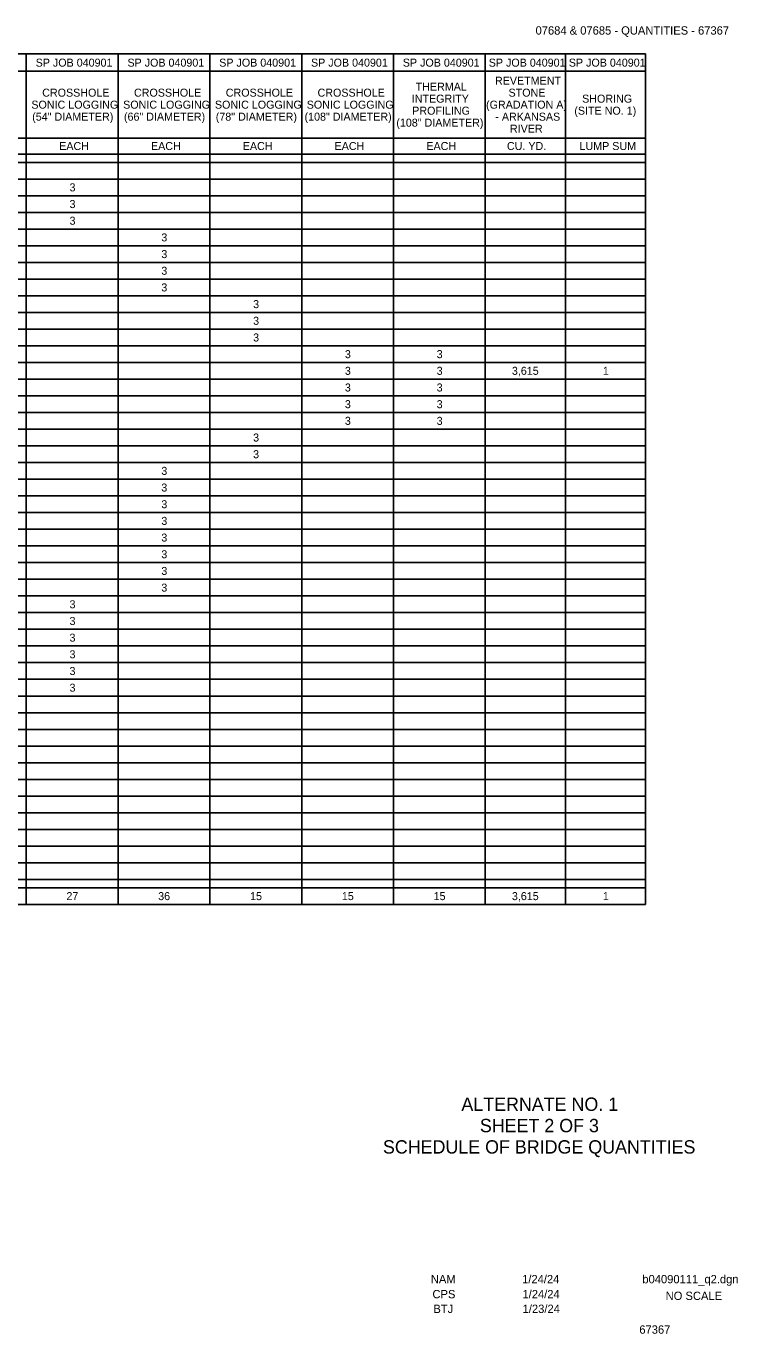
# Model space of a CAD drawing. Extents: x 0.06 to 1.36, y 0.04 to 0.85.
# Drawn here: x 0.914 to 1.358, y 0.037 to 0.854 of the extents above; entities that cross this region are included whole.
import ezdxf

# ---------------------------------------------------------------- set-up
doc = ezdxf.new("R2010")
doc.units = 0
doc.layers.add('R_Shade By Others', color=7, linetype='Continuous')
doc.layers.add('R_Survey Control', color=7, linetype='Continuous')

msp = doc.modelspace()

# ---------------------------------------------------------------- linework, layer by layer
at = {"layer": 'R_Survey Control'}
for p, q in [((0.07508, 0.83695), (1.30054, 0.83695)), ((0.9141, 0.83695), (0.9141, 0.3057)), ((0.97139, 0.83695), (0.97139, 0.3057)), ((1.02868, 0.83695), (1.02868, 0.3057)), ((1.08598, 0.83695), (1.08598, 0.3057)), ((1.14327, 0.83695), (1.14327, 0.3057)), ((1.20056, 0.83695), (1.20056, 0.3057)), ((1.25055, 0.83695), (1.25055, 0.3057)), ((1.30054, 0.83695), (1.30054, 0.3057)), ((0.2593, 0.78445), (1.30054, 0.78445)), ((0.07508, 0.77445), (1.30054, 0.77445)), ((0.11154, 0.76924), (1.30054, 0.76924)), ((0.11154, 0.75883), (1.30054, 0.75883)), ((0.11154, 0.74841), (1.30054, 0.74841)), ((0.11154, 0.73799), (1.30054, 0.73799)), ((0.11154, 0.72758), (1.30054, 0.72758)), ((0.11154, 0.71716), (1.30054, 0.71716)), ((0.11154, 0.70674), (1.30054, 0.70674)), ((0.11154, 0.69633), (1.30054, 0.69633)), ((0.11154, 0.68591), (1.30054, 0.68591)), ((0.11154, 0.67549), (1.30054, 0.67549)), ((0.11154, 0.66508), (1.30054, 0.66508)), ((0.11154, 0.65466), (1.30054, 0.65466)), ((0.11154, 0.64424), (1.30054, 0.64424)), ((0.11154, 0.63383), (1.30054, 0.63383)), ((0.11154, 0.62341), (1.30054, 0.62341)), ((0.11154, 0.61299), (1.30054, 0.61299)), ((0.11154, 0.60258), (1.30054, 0.60258)), ((0.11154, 0.59216), (1.30054, 0.59216)), ((0.11154, 0.58174), (1.30054, 0.58174)), ((0.11154, 0.57133), (1.30054, 0.57133)), ((0.11154, 0.56091), (1.30054, 0.56091)), ((0.11154, 0.55049), (1.30054, 0.55049)), ((0.11154, 0.54008), (1.30054, 0.54008)), ((0.11154, 0.52966), (1.30054, 0.52966)), ((0.11154, 0.51924), (1.30054, 0.51924)), ((0.11154, 0.50883), (1.30054, 0.50883)), ((0.11154, 0.49841), (1.30054, 0.49841)), ((0.11154, 0.48799), (1.30054, 0.48799)), ((0.11154, 0.47758), (1.30054, 0.47758)), ((0.11154, 0.46716), (1.30054, 0.46716)), ((0.11154, 0.45674), (1.30054, 0.45674)), ((0.11154, 0.44633), (1.30054, 0.44633)), ((0.11154, 0.43591), (1.30054, 0.43591)), ((0.11154, 0.42549), (1.30054, 0.42549)), ((0.11154, 0.41508), (1.30054, 0.41508)), ((0.11154, 0.40466), (1.30054, 0.40466)), ((0.11154, 0.39424), (1.30054, 0.39424)), ((0.11154, 0.38383), (1.30054, 0.38383)), ((0.11154, 0.37341), (1.30054, 0.37341)), ((0.11154, 0.36299), (1.30054, 0.36299)), ((0.11154, 0.35258), (1.30054, 0.35258)), ((0.11154, 0.34216), (1.30054, 0.34216)), ((0.11154, 0.33174), (1.30054, 0.33174)), ((0.11154, 0.32133), (1.30054, 0.32133)), ((0.07508, 0.31612), (1.30054, 0.31612)), ((0.07508, 0.3057), (1.30054, 0.3057))]:
    msp.add_line(p, q, dxfattribs=at)
msp.add_lwpolyline([(0.2593, 0.82612), (0.30758, 0.82612), (0.36154, 0.82612), (0.40321, 0.82612), (0.44487, 0.82612), (0.49175, 0.82612), (0.52821, 0.82612), (0.58029, 0.82612), (0.64019, 0.82612), (0.7079, 0.82612), (0.75998, 0.82612), (0.81206, 0.82612), (0.85894, 0.82612), (0.86623, 0.82612), (0.92873, 0.82612), (0.99644, 0.82612), (1.06415, 0.82612), (1.11623, 0.82612), (1.16831, 0.82612), (1.30054, 0.82612)], dxfattribs=at)

# ---------------------------------------------------------------- texts
at = {"layer": 'R_Shade By Others'}
for s, height, p in [('07684 & 07685 - QUANTITIES - 67367', 0.0052083, (1.23195, 0.84904)), ('ALTERNATE NO. 1', 0.0083332, (1.18566, 0.17677)), ('SHEET 2 OF 3', 0.0083332, (1.1972, 0.16344)), ('SCHEDULE OF BRIDGE QUANTITIES', 0.0083332, (1.13669, 0.1501)), ('NAM', 0.005208, (1.1666, 0.06906)), ('1/24/24', 0.005208, (1.22357, 0.06906)), ('b04090111_q2.dgn', 0.0052083, (1.29862, 0.06906)), ('CPS', 0.005208, (1.1676, 0.05969)), ('1/24/24', 0.005208, (1.22378, 0.05969)), ('NO SCALE', 0.005208, (1.31316, 0.05864)), ('BTJ', 0.005208, (1.16819, 0.05052)), ('1/23/24', 0.005208, (1.22389, 0.05052)), ('67367', 0.005208, (1.29672, 0.03756))]:
    msp.add_text(s, height=height, dxfattribs=at).set_placement(p)
at = {"layer": 'R_Survey Control'}
for s, p in [('SP JOB 040901', (0.91992, 0.82904)), ('SP JOB 040901', (0.97721, 0.82904)), ('SP JOB 040901', (1.0345, 0.82904)), ('SP JOB 040901', (1.09179, 0.82904)), ('SP JOB 040901', (1.14909, 0.82904)), ('SP JOB 040901', (1.20273, 0.82904)), ('SP JOB 040901', (1.25271, 0.82904)), ('THERMAL', (1.15711, 0.81404)), ('REVETMENT ', (1.20662, 0.81779)), ('CROSSHOLE', (0.92401, 0.81029)), ('CROSSHOLE', (0.9813, 0.81029)), ('CROSSHOLE', (1.03859, 0.81029)), ('CROSSHOLE', (1.09588, 0.81029)), ('INTEGRITY', (1.15468, 0.80654)), ('STONE ', (1.21509, 0.81029)), ('SHORING', (1.26103, 0.80654)), ('SONIC LOGGING', (0.91724, 0.80279)), ('(54" DIAMETER)', (0.91776, 0.79529)), ('SONIC LOGGING', (0.97453, 0.80279)), ('(66" DIAMETER)', (0.97505, 0.79529)), ('SONIC LOGGING', (1.03182, 0.80279)), ('(78" DIAMETER)', (1.03235, 0.79529)), ('(108" DIAMETER)', (1.08776, 0.79529)), ('SONIC LOGGING', (1.08912, 0.80279)), ('PROFILING', (1.15496, 0.79904)), ('(GRADATION A)', (1.20106, 0.80279)), ('(SITE NO. 1)', (1.25616, 0.79904)), ('(108" DIAMETER)', (1.14505, 0.79154)), ('- ARKANSAS', (1.20685, 0.79529)), ('RIVER', (1.21597, 0.78779)), ('EACH', (0.93462, 0.77695)), ('EACH', (0.99191, 0.77695)), ('EACH', (1.04921, 0.77695)), ('EACH', (1.1065, 0.77695)), ('EACH', (1.16379, 0.77695)), ('CU. YD.', (1.21409, 0.77695)), ('LUMP SUM', (1.25939, 0.77695)), ('3', (0.94107, 0.75112)), ('3', (0.94107, 0.7407)), ('3', (0.94107, 0.73029)), ('3', (0.99836, 0.71987)), ('3', (0.99836, 0.70945)), ('3', (0.99836, 0.69904)), ('3', (0.99836, 0.68862)), ('3', (1.05565, 0.6782)), ('3', (1.05565, 0.66779)), ('3', (1.05565, 0.65737)), ('3', (1.11294, 0.64695)), ('3', (1.17023, 0.64695)), ('3', (1.11294, 0.63654)), ('3', (1.17023, 0.63654)), ('3,615', (1.21719, 0.63654)), ('1', (1.27394, 0.63654)), ('3', (1.11294, 0.62612)), ('3', (1.17023, 0.62612)), ('3', (1.11294, 0.6157)), ('3', (1.17023, 0.6157)), ('3', (1.11294, 0.60529)), ('3', (1.17023, 0.60529)), ('3', (1.05565, 0.59487)), ('3', (1.05565, 0.58445)), ('3', (0.99836, 0.57404)), ('3', (0.99836, 0.56362)), ('3', (0.99836, 0.5532)), ('3', (0.99836, 0.54279)), ('3', (0.99836, 0.53237)), ('3', (0.99836, 0.52195)), ('3', (0.99836, 0.51154)), ('3', (0.99836, 0.50112)), ('3', (0.94107, 0.4907)), ('3', (0.94107, 0.48029)), ('3', (0.94107, 0.46987)), ('3', (0.94107, 0.45945)), ('3', (0.94107, 0.44904)), ('3', (0.94107, 0.43862)), ('27', (0.93912, 0.30841)), ('36', (0.9964, 0.30841)), ('15', (1.05376, 0.30841)), ('15', (1.11105, 0.30841)), ('15', (1.16834, 0.30841)), ('3,615', (1.21719, 0.30841)), ('1', (1.27394, 0.30841))]:
    msp.add_text(s, height=0.005, dxfattribs=at).set_placement(p)

doc.saveas('drawing.dxf')
